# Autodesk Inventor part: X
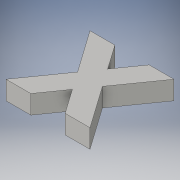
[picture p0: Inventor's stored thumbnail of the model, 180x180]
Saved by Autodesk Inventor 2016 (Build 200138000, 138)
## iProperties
Created: 2017-05
Part Number: X
Material: Glass
Document SubType Name: Modeling
Designer: 8643301
Density: 2.18 g/cm^3
Appearance: Clear
Author: 8643301
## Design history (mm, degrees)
sketch "Sketch1"
  geometry: L1 (0, 0)-(-6.76, 0); L2 (-6.76, 0)-(-22.86, -22.86); L3 (-22.86, -22.86)-(-16.1, -22.86); L4 (-16.1, -22.86)-(0, 0); L5 (0, -22.86)-(-6.76, -22.86); L6 (-6.76, -22.86)-(-22.86, 0); L7 (-22.86, 0)-(-16.1, 0); L8 (-16.1, 0)-(0, -22.86)
  constraints: 16 end point, 4 point on line, 3 equal length, 2 vertical alignment, 1 horizontal, 1 parallel
  dimensions: "d8" = 70.3118 deg angle of L4 L6; "d9" = 22.86 distance of L5.start L2.end; "d10" = 22.86 distance of L1.start L5.start
extrude "Extrusion1" new body sketch "Sketch1" distance "d5" = 5.08; taper "d6" = 0 deg
body "Solid1"
